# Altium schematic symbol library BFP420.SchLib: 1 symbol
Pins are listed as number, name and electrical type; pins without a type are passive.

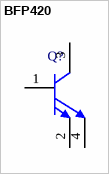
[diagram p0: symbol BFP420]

## BFP420
designator Q?
NPN Silicon RF Transistor, 4.5 V VCEO, 35 mA IC, 21 dB Gmax, SOT343, Green; Manufacturer: Infineon; PartNumber: BFP420; Gmax (typ): 21 dB; Green: yes; IC (max): 35 mA; NFmin (typ): 1.1 dB; Ptot (max): 160 mW; VCEO (max): 4.5 V
footprint INF-SOT343_V (SOT343, 4-Leads, Body 2x1.25 mm)
pins: 1 B, 2 E, 3 C, 4 E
